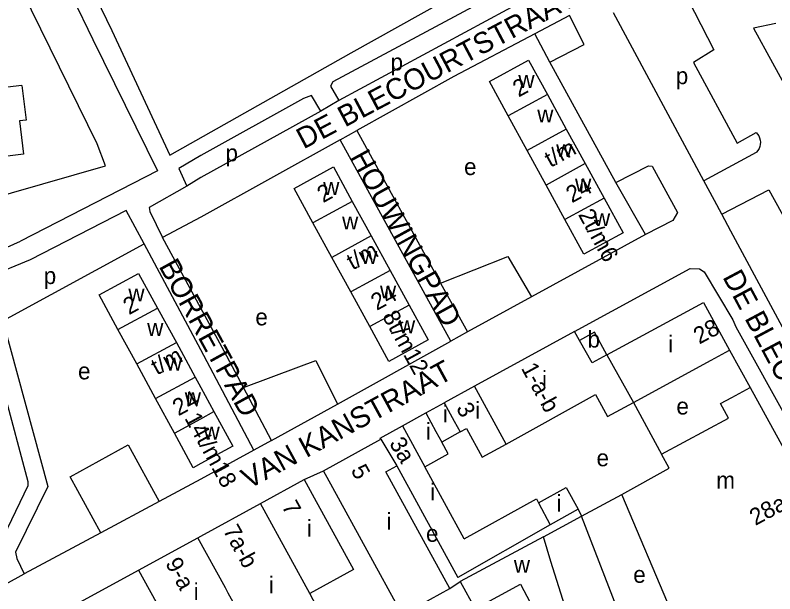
# Model space of a CAD drawing. Extents: x 157569 to 159501, y 382907 to 384670.
# Drawn here: x 159055.8 to 159236.8, y 383350.2 to 383488.1 of the extents above; entities that cross this region are included whole.
import ezdxf

# ---------------------------------------------------------------- set-up
doc = ezdxf.new("R2010")
doc.units = 0
for name, color, linetype in [('BLT_Basislijn', 7, 'Continuous'), ('BLT_Bebouwing', 7, 'Continuous'), ('BLT_Centroide', 7, 'Continuous'), ('BLT_Huisnummer', 7, 'Continuous'), ('BLT_Huisnummer_reeks', 7, 'Continuous'), ('BLT_Onderdoorgang_en_onderverdeling', 7, 'Continuous'), ('BLT_Onderverdeling_panden', 7, 'Continuous'), ('BLT_Straatnaam', 7, 'Continuous'), ('BLT_Straatnaam_verkleind', 7, 'Continuous')]:
    doc.layers.add(name, color=color, linetype=linetype)

msp = doc.modelspace()

# ---------------------------------------------------------------- linework, layer by layer
at = {"layer": 'BLT_Basislijn'}
for p, q in [((159053.97, 383536.19), (159078.77, 383484.5)), ((159063.57, 383504.54), (159074.27, 383482.33)), ((159177.9, 383492.21), (159132.86, 383467.78)), ((159187.83, 383488.08), (159179.57, 383483.66)), ((159219.83, 383448.65), (159198.33, 383488.68)), ((159074.27, 383482.33), (159089.69, 383451.03)), ((159183.2, 383476.96), (159179.57, 383483.66)), ((159198.91, 383448.23), (159183.2, 383476.96)), ((159132.86, 383467.78), (159128.62, 383465.27)), ((159133.18, 383458.42), (159137.14, 383460.62)), ((159137.14, 383460.62), (159157.15, 383424.26)), ((159159.55, 383410.4), (159133.18, 383458.42)), ((159232.31, 383455.36), (159219.83, 383448.65)), ((159089.69, 383451.03), (159057.07, 383434.28)), ((159205.93, 383435.82), (159198.91, 383448.23)), ((159222.37, 383443.94), (159219.83, 383448.65)), ((159224.12, 383440.67), (159222.37, 383443.94)), ((159082.22, 383441.57), (159059.36, 383429.83)), ((159086.49, 383433.6), (159082.22, 383441.57)), ((159226.27, 383436.67), (159224.12, 383440.67)), ((159205.93, 383435.82), (159178.8, 383421)), ((159049.58, 383430.87), (159057.07, 383434.28)), ((159052.79, 383415.23), (159086.49, 383433.6)), ((159157.15, 383424.26), (159163.53, 383412.67)), ((159178.8, 383421), (159163.53, 383412.67)), ((159163.53, 383412.67), (159159.55, 383410.4)), ((159132.55, 383395.43), (159159.55, 383410.4)), ((159225.97, 383408.25), (159230.93, 383399.4)), ((159116.82, 383386.71), (159110.16, 383399.34)), ((159116.82, 383386.71), (159132.55, 383395.43)), ((159203.06, 383395.81), (159209.75, 383383.5)), ((159116.82, 383386.71), (159112.6, 383384.39)), ((159124.65, 383377.42), (159129.2, 383379.53)), ((159190.74, 383368.68), (159200.32, 383373.83)), ((159090.05, 383372.15), (159076.17, 383364.7)), ((159189.9, 383370.38), (159190.74, 383368.68)), ((159076.17, 383364.7), (159057.95, 383354.93)), ((159159.35, 383351.46), (159161.82, 383353.07))]:
    msp.add_line(p, q, dxfattribs=at)
for points in [[(159135.84, 383479.15), (159179.6, 383503.66), (159192.82, 383510.27), (159201.35, 383513.95)], [(159010.57, 383433.04), (159077.27, 383452.24), (159075.29, 383457.44), (159052.92, 383503.15)], [(159175.9, 383496.15), (159131.49, 383472.24), (159130.94, 383471.25), (159132.86, 383467.78)], [(159214.56, 383494.96), (159222.2, 383479.9), (159217.4, 383476.86), (159227.76, 383457.63), (159232.31, 383460.16)], [(159183.2, 383476.96), (159191.35, 383481.16), (159187.83, 383488.08)], [(159237.05, 383486.13), (159231.69, 383485.04), (159240.73, 383468.5)], [(159078.77, 383484.5), (159092.62, 383454.77), (159135.84, 383479.15)], [(159179.57, 383483.66), (159160.25, 383473.51), (159137.14, 383460.62)], [(159128.62, 383465.27), (159126.37, 383468.98), (159124.46, 383468.27), (159100, 383454.65), (159094.73, 383451.61), (159096.67, 383447.34)], [(159128.62, 383465.27), (159100, 383449.43), (159096.67, 383447.34)], [(159232.31, 383460.16), (159232.66, 383459.78), (159232.93, 383459.34), (159233.14, 383458.86), (159233.27, 383458.36), (159233.33, 383457.85), (159233.3, 383457.33), (159233.19, 383456.82), (159233.01, 383456.34), (159232.76, 383455.89), (159232.44, 383455.48), (159232.31, 383455.36)], [(159133.18, 383458.42), (159100, 383439.94), (159090.9, 383435.16)], [(159198.91, 383448.23), (159206.67, 383452.23), (159207.57, 383452.13), (159213.58, 383441.07), (159212.46, 383439.22), (159205.93, 383435.82)], [(159096.67, 383447.34), (159087.73, 383442.27), (159087.86, 383441.36), (159090.9, 383435.16)], [(159224.12, 383440.67), (159235.35, 383446.5), (159257.09, 383407.04), (159250.77, 383403.75), (159253.05, 383399.45), (159247.93, 383396.5)], [(159247.93, 383396.5), (159245.87, 383400.19), (159226.27, 383436.67)], [(159110.16, 383399.34), (159105.59, 383408.02), (159100, 383418.26), (159090.9, 383435.16)], [(159112.6, 383384.39), (159100, 383408.33), (159086.49, 383433.6)], [(159059.36, 383429.83), (159049.68, 383425.86), (159050.03, 383425.36)], [(159157.15, 383424.26), (159173.15, 383430.57), (159178.8, 383421)], [(159189.07, 383412.73), (159216.6, 383427.73), (159218.83, 383427.65), (159219.95, 383426.96), (159226.79, 383415.5), (159227.49, 383413.81), (159254.26, 383365.56), (159262.09, 383350.88)], [(159052.79, 383415.23), (159063.54, 383375.73), (159055.87, 383360.08), (159056.14, 383358.62), (159057.95, 383354.93)], [(159110.16, 383399.34), (159123.34, 383404.26), (159127.38, 383405.78), (159132.55, 383395.43)], [(159028.76, 383391.86), (159050.35, 383403.64), (159051.14, 383403.8), (159053, 383398.73), (159058.78, 383376.99), (159058.82, 383375.95), (159049, 383355.73)], [(159076.17, 383364.7), (159068.87, 383378.07), (159082.67, 383385.69), (159090.05, 383372.15)], [(159112.6, 383384.39), (159100, 383377.49), (159090.05, 383372.15)], [(159049, 383355.73), (159052.52, 383352.54), (159053.48, 383352.51), (159057.95, 383354.93)]]:
    msp.add_lwpolyline(points, dxfattribs=at)
at = {"layer": 'BLT_Bebouwing'}
for p, q in [((159182.58, 383469.22), (159187.08, 383460.98)), ((159177.75, 383455.88), (159173.24, 383464.11)), ((159187.08, 383460.98), (159191.59, 383452.75)), ((159182.26, 383447.64), (159177.75, 383455.88)), ((159191.59, 383452.75), (159196.1, 383444.51)), ((159186.76, 383439.4), (159182.26, 383447.64)), ((159136.08, 383443.75), (159140.59, 383435.51)), ((159131.25, 383430.39), (159126.73, 383438.63)), ((159140.59, 383435.51), (159145.11, 383427.26)), ((159135.76, 383422.14), (159131.25, 383430.39)), ((159145.11, 383427.26), (159149.62, 383419.02)), ((159140.27, 383413.9), (159135.76, 383422.14)), ((159219.77, 383419.64), (159225.97, 383408.25)), ((159089.68, 383418.32), (159094.17, 383410.08)), ((159084.75, 383404.97), (159080.27, 383413.22)), ((159189.07, 383412.73), (159165.23, 383399.67)), ((159190.23, 383410.61), (159189.07, 383412.73)), ((159094.17, 383410.08), (159098.65, 383401.85)), ((159089.22, 383396.73), (159084.75, 383404.97)), ((159165.23, 383399.67), (159157.99, 383395.71)), ((159230.93, 383399.4), (159255.71, 383353.81)), ((159093.7, 383388.49), (159089.22, 383396.73)), ((159153.61, 383393.3), (159157.99, 383395.71)), ((159148.02, 383390.24), (159153.61, 383393.3)), ((159161.8, 383388.78), (159157.4, 383386.37)), ((159129.2, 383379.53), (159142.87, 383387.02)), ((159211.57, 383380.13), (159209.75, 383383.5)), ((159146.69, 383380.71), (159161.27, 383354.09)), ((159162.72, 383363.31), (159153.35, 383380.48)), ((159200.32, 383373.83), (159211.57, 383380.13)), ((159114.2, 383371.7), (159124.65, 383377.42)), ((159213.51, 383342.64), (159200.32, 383373.83)), ((159181.63, 383363.77), (159190.74, 383368.68)), ((159200.04, 383344.48), (159190.74, 383368.68)), ((159183.26, 383366.61), (159161.27, 383354.09)), ((159085.19, 383355.8), (159099.28, 383363.52)), ((159181.63, 383363.77), (159161.82, 383353.07)), ((159070.49, 383347.75), (159085.19, 383355.8)), ((159132.8, 383337.38), (159125.96, 383350.24)), ((159152.4, 383347.65), (159159.35, 383351.46))]:
    msp.add_line(p, q, dxfattribs=at)
for points in [[(159057.37, 383471.41), (159047.15, 383470.15), (159046.93, 383471.93), (159041.38, 383471.24), (159040.83, 383475.7), (159048.85, 383476.68)], [(159173.24, 383464.11), (159168.75, 383472.32), (159178.08, 383477.43), (159182.58, 383469.22)], [(159057.37, 383471.41), (159058.39, 383463.14), (159056.82, 383462.94), (159057.79, 383455.03), (159049.43, 383454), (159049.23, 383455.64), (159039.99, 383454.5), (159041.24, 383444.3), (159038.05, 383443.9), (159033.33, 383443.31)], [(159126.73, 383438.63), (159122.24, 383446.84), (159131.59, 383451.96), (159136.08, 383443.75)], [(159196.1, 383444.51), (159200.61, 383436.27), (159191.27, 383431.16), (159186.76, 383439.4)], [(159080.27, 383413.22), (159075.8, 383421.46), (159085.19, 383426.56), (159089.68, 383418.32)], [(159149.62, 383419.02), (159154.14, 383410.77), (159144.82, 383405.6), (159140.27, 383413.9)], [(159196.71, 383407.18), (159219.77, 383419.64)], [(159196.71, 383407.18), (159193.77, 383412.55), (159190.23, 383410.61)], [(159203.06, 383395.81), (159221.58, 383405.85), (159225.97, 383408.25)], [(159098.65, 383401.85), (159100, 383399.38), (159103.14, 383393.62)], [(159209.75, 383383.5), (159225.73, 383392.07), (159223.84, 383395.55), (159226.49, 383396.99), (159230.93, 383399.4)], [(159172.72, 383385.89), (159194.03, 383397.72), (159196.89, 383392.46), (159203.06, 383395.81)], [(159103.14, 383393.62), (159107.63, 383385.38), (159100, 383381.24), (159098.17, 383380.24), (159093.7, 383388.49)], [(159142.87, 383387.02), (159142.7, 383387.32), (159148.02, 383390.24)], [(159161.8, 383388.78), (159163.29, 383389.61), (159167.05, 383382.77), (159172.72, 383385.89)], [(159153.35, 383380.48), (159158.94, 383383.56), (159157.4, 383386.37)], [(159159.35, 383351.46), (159144.1, 383379.29), (159146.69, 383380.71)], [(159147.8, 383345.57), (159131.42, 383375.48), (159129.2, 383379.53)], [(159124.65, 383377.42), (159127.05, 383373.04), (159136.41, 383355.96), (159125.96, 383350.24)], [(159180.48, 383371.89), (159187.07, 383375.52), (159189.9, 383370.38)], [(159099.28, 383363.52), (159100, 383363.92), (159114.2, 383371.7)], [(159162.72, 383363.31), (159179.98, 383372.83), (159180.48, 383371.89)], [(159189.9, 383370.38), (159183.26, 383366.61)], [(159161.82, 383353.07), (159165.38, 383346.61), (159176.15, 383352.51), (159180, 383345.26)]]:
    msp.add_lwpolyline(points, dxfattribs=at)
at = {"layer": 'BLT_Onderdoorgang_en_onderverdeling'}
msp.add_line((159180.48, 383371.89), (159183.26, 383366.61), dxfattribs=at)
for points in [[(159157.99, 383395.71), (159160.4, 383391.33), (159161.8, 383388.78)], [(159153.61, 383393.3), (159156.01, 383388.91), (159157.4, 383386.37)]]:
    msp.add_lwpolyline(points, dxfattribs=at)
at = {"layer": 'BLT_Onderverdeling_panden'}
for p, q in [((159182.58, 383469.22), (159173.24, 383464.11)), ((159187.08, 383460.98), (159177.75, 383455.88)), ((159191.59, 383452.75), (159182.26, 383447.64)), ((159196.1, 383444.51), (159186.76, 383439.4)), ((159136.08, 383443.75), (159126.73, 383438.63)), ((159140.59, 383435.51), (159131.25, 383430.39)), ((159145.11, 383427.26), (159135.76, 383422.14)), ((159149.62, 383419.02), (159140.27, 383413.9)), ((159080.27, 383413.22), (159089.68, 383418.32)), ((159084.75, 383404.97), (159094.17, 383410.08)), ((159196.71, 383407.18), (159203.06, 383395.81)), ((159089.22, 383396.73), (159098.65, 383401.85)), ((159172.72, 383385.89), (159165.23, 383399.67)), ((159148.02, 383390.24), (159153.35, 383380.48)), ((159142.87, 383387.02), (159146.69, 383380.71)), ((159121.43, 383358.49), (159114.2, 383371.7)), ((159105.86, 383351.57), (159099.28, 383363.52)), ((159125.96, 383350.24), (159121.43, 383358.49)), ((159085.19, 383355.8), (159091.74, 383343.84)), ((159106.53, 383350.32), (159105.86, 383351.57)), ((159111.41, 383341.61), (159106.53, 383350.32))]:
    msp.add_line(p, q, dxfattribs=at)
for points in [[(159196.71, 383407.18), (159193.22, 383405.27), (159190.23, 383410.61)], [(159093.7, 383388.49), (159100, 383391.91), (159103.14, 383393.62)], [(159186.71, 383347.31), (159183.44, 383357.9), (159181.63, 383363.77)]]:
    msp.add_lwpolyline(points, dxfattribs=at)

# ---------------------------------------------------------------- texts
at = {"layer": 'BLT_Centroide'}
for s, p in [('p', (159145.21, 383474.97)), ('p', (159213.17, 383471.69)), ('w', (159175.66, 383470.78)), ('w', (159180.16, 383462.56)), ('w', (159184.67, 383454.31)), ('p', (159105.87, 383453.3)), ('e', (159162.73, 383450.02)), ('w', (159129.16, 383445.28)), ('w', (159189.17, 383446.06)), ('w', (159193.69, 383437.84)), ('w', (159133.66, 383437.06)), ('w', (159138.18, 383428.81)), ('p', (159062.57, 383424.03)), ('w', (159082.74, 383419.88)), ('w', (159142.69, 383420.59)), ('e', (159113, 383414.18)), ('w', (159147.22, 383412.31)), ('w', (159087.22, 383411.66)), ('b', (159192.14, 383408.89)), ('i', (159211.39, 383407.75)), ('w', (159091.7, 383403.41)), ('e', (159070.75, 383401.3)), ('i', (159181.3, 383399.31)), ('w', (159096.18, 383395.16)), ('i', (159157.7, 383391.05)), ('i', (159165.36, 383391.97)), ('e', (159213.32, 383392.92)), ('w', (159100.66, 383386.94)), ('i', (159153.59, 383386.95)), ('e', (159194.29, 383380.58)), ('m', (159222.82, 383375.28)), ('i', (159154.62, 383372.48)), ('i', (159184.73, 383369.76)), ('i', (159144.27, 383365.48)), ('i', (159125.3, 383363.83)), ('e', (159153.66, 383362.57)), ('w', (159174.59, 383355.19)), ('e', (159203.04, 383352.79)), ('i', (159116.19, 383350.31)), ('i', (159098.3, 383348.69))]:
    msp.add_text(s, height=4, dxfattribs=at).set_placement(p)
at = {"layer": 'BLT_Huisnummer'}
for s, rotation, p in [('28', 28.5235, (159218.77, 383409.58)), ('3', 298.7162, (159160.73, 383394.46)), ('3a', 301.217, (159144.78, 383386.05)), ('5', 298.7165, (159135.64, 383379.66)), ('7', 298.7193, (159119.17, 383371.05))]:
    msp.add_text(s, height=4, rotation=rotation, dxfattribs=at).set_placement(p)
at = {"layer": 'BLT_Huisnummer_reeks'}
for s, rotation, p in [('2', 28.687, (159175.72, 383468.49)), ('t/m', 28.687, (159183.31, 383451.71)), ('2', 28.7027, (159129.13, 383443.3)), ('24', 28.6822, (159188.42, 383443.26)), ('2t/m6', 298.6862, (159189.82, 383440.61)), ('t/m', 28.7027, (159136.16, 383427.26)), ('24', 28.5442, (159141.92, 383417.63)), ('2', 28.4927, (159082.88, 383416.59)), ('8t/m12', 298.7026, (159143.14, 383416.39)), ('t/m', 28.495, (159089.54, 383402.22)), ('1-a-b', 298.5172, (159176.23, 383403.98)), ('24', 28.5442, (159094.66, 383392.47)), ('14t/m18', 298.5876, (159096.03, 383392.06)), ('28a-30', 28.5235, (159232.13, 383366.34)), ('7a-b', 298.7132, (159105.21, 383365.31)), ('9-a', 298.7147, (159091.45, 383357.47))]:
    msp.add_text(s, height=4, rotation=rotation, dxfattribs=at).set_placement(p)
at = {"layer": 'BLT_Straatnaam'}
for s, height, rotation, p in [('DE BLECOURTSTRAAT', 5, 27.952, (159124.5, 383456.11)), ('HOUWINGPAD', 5, 298.821, (159135.38, 383454.32)), ('BORRETPAD', 5, 298.821, (159089.88, 383428.29)), ('DE BLECOURTSTRAAT', 4.9999, 298.1013, (159224.22, 383425.72)), ('VAN KANSTRAAT', 5, 28.6022, (159111.43, 383375.04))]:
    msp.add_text(s, height=height, rotation=rotation, dxfattribs=at).set_placement(p)
at = {"layer": 'BLT_Straatnaam_verkleind'}
msp.add_text('JACOB OPPENHEIMSTRAAT', height=4, rotation=322.9024, dxfattribs=at).set_placement((158999.97, 383383.43))

doc.saveas('drawing.dxf')
